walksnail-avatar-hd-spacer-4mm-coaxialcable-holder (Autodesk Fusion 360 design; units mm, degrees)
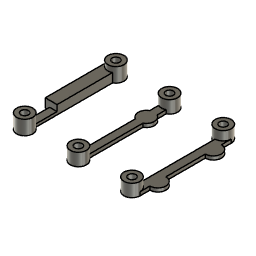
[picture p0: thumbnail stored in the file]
sketch "Skizze" plane through (0, 0, 0) normal (0, 0, 1) x axis (1, 0, 0)
  line L1 (-2.25, 8) -> (-2.25, 17)
  line L2 (1.05, 23.51) -> (1.05, 1.99)
  line L3 (-2.25, 8) -> (1.05, 8)
  line L4 (-1.05, 8) -> (-1.05, 0)
  line L5 (-2.25, 25.5) -> (-2.25, 17)
  line L6 (13.95, 20.99) -> (13.95, 23.51)
  line L7 (16.05, 23.51) -> (16.05, 20.99)
  line L8 (13.95, 17.01) -> (13.95, 0)
  line L9 (16.05, 17.01) -> (16.05, 0)
  line L10 (32.25, 25.5) -> (32.25, 0)
  line L11 (30, 23.25) -> (30, 2.25)
  circle C1 centre (0, 0) radius 1.05
  circle C2 centre (0, 0) radius 2.25
  circle C3 centre (0, 25.5) radius 1.05
  circle C4 centre (0, 25.5) radius 2.25
  circle C5 centre (15, 0) radius 2.25
  circle C6 centre (15, 0) radius 1.05
  circle C7 centre (15, 25.5) radius 1.05
  circle C8 centre (15, 25.5) radius 2.25
  circle C9 centre (15, 19) radius 2.25
  circle C10 centre (30, 0) radius 1.05
  circle C11 centre (30, 0) radius 2.25
  circle C12 centre (32.25, 20.5) radius 2.25
  circle C13 centre (30, 25.5) radius 2.25
  circle C14 centre (30, 25.5) radius 1.05
  circle C15 centre (32.25, 5) radius 2.25
  point P1 (0, 0)
  point P2 (0, 0)
  point P6 (1.05, 23.51)
  point P7 (1.05, 1.99)
  point P9 (1.05, 8)
  point P11 (-1.05, 0)
  point P12 (-1.05, 8)
  point P17 (16.05, 23.51)
  point P18 (-2.25, 25.5)
  point P20 (13.95, 20.99)
  point P21 (16.05, 20.99)
  point P22 (13.95, 23.51)
  point P23 (13.95, 0)
  point P24 (13.95, 17.01)
  point P25 (16.05, 0)
  point P26 (16.05, 17.01)
  point P33 (32.25, 0)
  point P34 (32.25, 25.5)
  point P35 (30, 23.25)
  point P36 (30, 2.25)
  coincident P1 P2
  concentric C1 C2
  concentric C3 C4
  tangent C2 L1
  vertical L1
  tangent C3 L2
  parallel L1 L2
  coincident C4 P6
  coincident C2 P7
  perpendicular L1 L3
  coincident L2 P9
  coincident C1 P11
  coincident L3 P12
  tangent C1 L4
  perpendicular L3 L4
  concentric C5 C6
  concentric C7 C8
  coincident P17 C8
  tangent C6 L6
  vertical L6
  coincident C4 P18
  tangent C4 L5
  coincident C9 P20
  coincident C9 P21
  coincident C8 P22
  coincident C6 P23
  coincident C9 P24
  tangent C6 L8
  vertical L8
  coincident C6 P25
  coincident C9 P26
  tangent C6 L9
  parallel L8 L9
  concentric C10 C11
  concentric C13 C14
  coincident C11 P33
  coincident C13 P34
  tangent C13 L10
  vertical L10
  coincident C13 P35
  parallel L10 L11
  coincident C11 P36
  dimension "d1" diameter C1 = 2.1
  dimension "d2" diameter C2 = 4.5
  dimension "d3" diameter C3 = 2.1
  dimension "d4" diameter C4 = 4.5
  dimension "d11" diameter C6 = 2.1
  dimension "d12" diameter C5 = 4.5
  dimension "d13" diameter C7 = 2.1
  dimension "d14" diameter C8 = 4.5
  dimension "d15" diameter C9 = 4.5
  dimension "d22" diameter C10 = 2.1
  dimension "d23" diameter C11 = 4.5
  dimension "d24" diameter C14 = 2.1
  dimension "d25" diameter C13 = 4.5
  dimension "d26" diameter C12 = 4.5
  dimension "d27" diameter C15 = 4.5
extrude "Extrusion1" new body sketch "Skizze" profile of C1 C2 C3 C4 along normal blind 4 bodies "Walksnail-Avatar-HD-Spacer-4mm + coaxialcable-holder"
extrude "Extrusion2" add sketch "Skizze" profile of C2 C4 L2 L3 L4 along normal blind 0.8
extrude "Extrusion3" add sketch "Skizze" profile of L1 L2 L3 along normal blind 2.5
extrude "Extrusion4" new body sketch "Skizze" profile of C5 C6 C7 C8 along normal blind 3.5 bodies "Walksnail-Avatar-HD-Spacer-3,5mm + ipex-holder"
extrude "Extrusion5" add sketch "Skizze" profile of C5 C8 L7 L6 C9 along normal blind 1
extrude "Extrusion6" add sketch "Skizze" profile of C9 along normal blind 1
extrude "Extrusion7" new body sketch "Skizze" profile of C10 C11 C13 C14 along normal blind 3.5 bodies "Walksnail-Avatar-HD-Spacer-3,5mm + 2x-ipex-holder"
extrude "Extrusion8" add sketch "Skizze" profile of C11 C12 C13 C15 along normal blind 1
named bodies: "Walksnail-Avatar-HD-Spacer-4mm + coaxialcable-holder", "Walksnail-Avatar-HD-Spacer-3,5mm + ipex-holder", "Walksnail-Avatar-HD-Spacer-3,5mm + 2x-ipex-holder"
